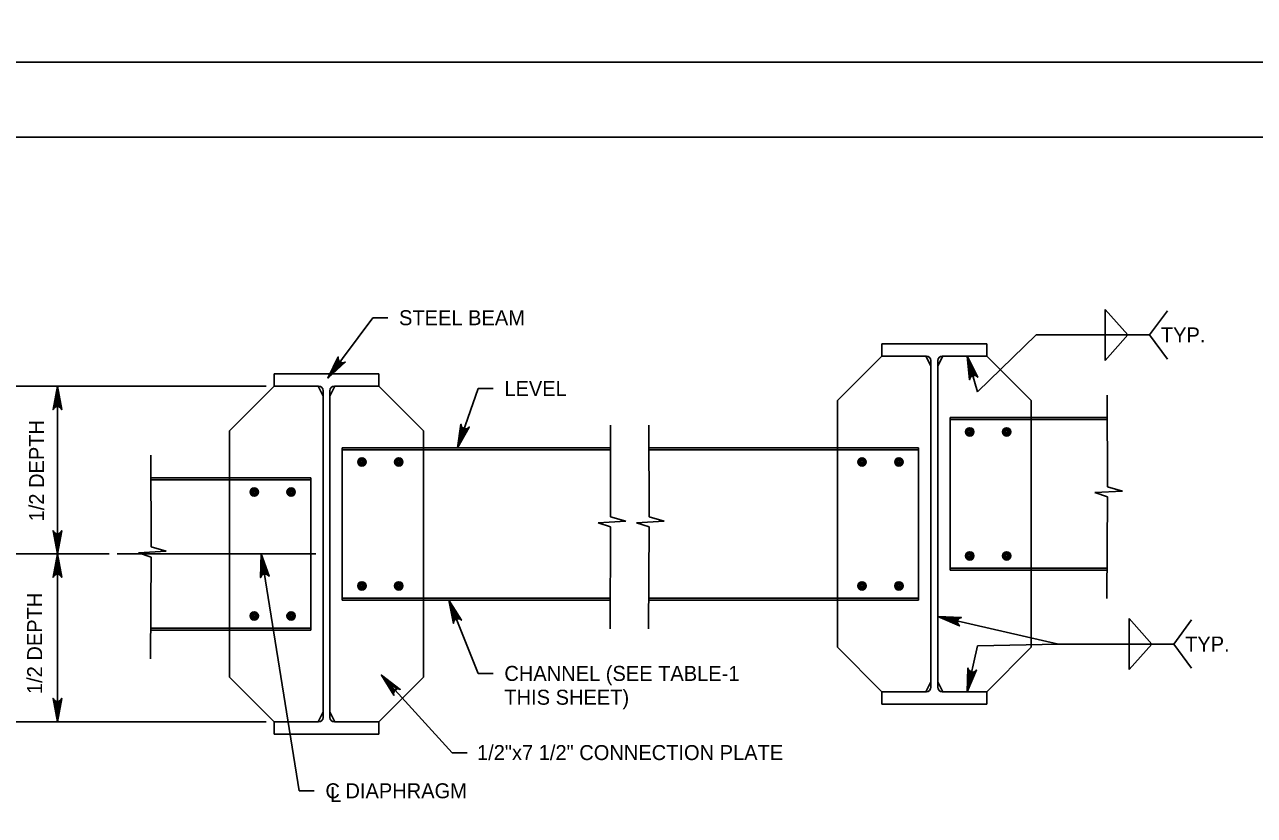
# Model space of a CAD drawing. Extents: x 638175 to 640495, y 294277 to 298435.
# Drawn here: x 639651.7 to 639897.7, y 297690.7 to 297849 of the extents above; entities that cross this region are included whole.
import ezdxf

# ---------------------------------------------------------------- set-up
doc = ezdxf.new("R2010")
doc.units = 0
for name, color, linetype in [('2', 7, 'Continuous'), ('3', 7, 'Continuous'), ('4', 7, 'Continuous'), ('5', 7, 'Continuous'), ('PLT-BNDY', 7, 'Continuous')]:
    doc.layers.add(name, color=color, linetype=linetype)

msp = doc.modelspace()

# ---------------------------------------------------------------- linework, layer by layer
at = {"layer": '2'}
msp.add_line((639316.46, 297826.46), (640102.46, 297826.46), dxfattribs=at)
for points in [[(639658.23, 297776.59), (639659.1, 297771.93), (639658.85, 297772.29), (639658.54, 297772.47), (639658.23, 297772.53), (639657.91, 297772.47), (639657.6, 297772.29), (639657.35, 297771.93), (639658.23, 297776.59), (639657.6, 297772.29), (639657.91, 297772.47), (639658.23, 297776.59), (639658.23, 297772.53), (639658.54, 297772.47), (639658.23, 297776.59), (639658.85, 297772.29)], [(639658.23, 297743.02), (639657.35, 297747.68), (639657.6, 297747.32), (639657.91, 297747.13), (639658.23, 297747.08), (639658.54, 297747.13), (639658.85, 297747.32), (639659.1, 297747.68), (639658.23, 297743.02), (639658.85, 297747.32), (639658.54, 297747.13), (639658.23, 297743.02), (639658.23, 297747.08), (639657.91, 297747.13), (639658.23, 297743.02), (639657.6, 297747.32)], [(639658.23, 297743.02), (639657.35, 297738.36), (639657.6, 297738.71), (639657.91, 297738.9), (639658.23, 297738.95), (639658.54, 297738.9), (639658.85, 297738.71), (639659.1, 297738.36), (639658.23, 297743.02), (639658.85, 297738.71), (639658.54, 297738.9), (639658.23, 297743.02), (639658.23, 297738.95), (639657.91, 297738.9), (639658.23, 297743.02), (639657.6, 297738.71)], [(639658.23, 297709.44), (639657.35, 297714.1), (639657.6, 297713.75), (639657.91, 297713.56), (639658.23, 297713.51), (639658.54, 297713.56), (639658.85, 297713.75), (639659.1, 297714.1), (639658.23, 297709.44), (639658.85, 297713.75), (639658.54, 297713.56), (639658.23, 297709.44), (639658.23, 297713.51), (639657.91, 297713.56), (639658.23, 297709.44), (639657.6, 297713.75)]]:
    msp.add_lwpolyline(points, dxfattribs=at)
at = {"layer": '3'}
for p, q in [((639712.33, 297778.21), (639721.32, 297790.3)), ((639721.32, 297790.3), (639724.32, 297790.3)), ((639867.84, 297791.93), (639872.38, 297786.85)), ((639867.84, 297786.85), (639867.84, 297791.93)), ((639876.75, 297786.85), (639880.32, 297791.69)), ((639842.3, 297775.45), (639854.05, 297786.85)), ((639854.05, 297786.85), (639876.75, 297786.85)), ((639867.84, 297781.76), (639872.38, 297786.85)), ((639867.84, 297786.85), (639867.84, 297781.76)), ((639876.75, 297786.85), (639880.32, 297782.01)), ((639840.22, 297782.6), (639842.3, 297775.45)), ((639700.02, 297776.59), (639634.16, 297776.59)), ((639658.23, 297743.02), (639658.23, 297776.59)), ((639738.25, 297764.29), (639742.4, 297776.14)), ((639742.4, 297776.14), (639745.4, 297776.14)), ((639868.25, 297774.83), (639868.31, 297756.48)), ((639768.85, 297768.82), (639768.91, 297750.46)), ((639776.57, 297768.82), (639776.63, 297750.46)), ((639676.89, 297762.81), (639676.95, 297744.45)), ((639871.31, 297755.6), (639865.79, 297755.29)), ((639865.79, 297755.29), (639868.3, 297754.43)), ((639868.31, 297756.48), (639871.31, 297755.6)), ((639868.3, 297754.43), (639868.18, 297734.08)), ((639768.91, 297750.46), (639771.92, 297749.58)), ((639776.63, 297750.46), (639779.63, 297749.58)), ((639771.92, 297749.58), (639766.4, 297749.28)), ((639766.4, 297749.28), (639768.91, 297748.42)), ((639768.91, 297748.42), (639768.79, 297728.06)), ((639779.63, 297749.58), (639774.11, 297749.28)), ((639774.11, 297749.28), (639776.63, 297748.42)), ((639776.63, 297748.42), (639776.5, 297728.06)), ((639668.59, 297743.02), (639649.76, 297743.02)), ((639658.23, 297709.44), (639658.23, 297743.02)), ((639679.96, 297743.57), (639674.44, 297743.26)), ((639674.44, 297743.26), (639676.95, 297742.41)), ((639676.95, 297744.45), (639679.96, 297743.57)), ((639698.98, 297743.02), (639706.59, 297695.63)), ((639676.95, 297742.41), (639676.83, 297722.05)), ((639736.53, 297733.77), (639742.4, 297719.13)), ((639834.37, 297730.53), (639858.54, 297725)), ((639872.68, 297730.08), (639877.21, 297725)), ((639872.68, 297725), (639872.68, 297730.08)), ((639881.59, 297725), (639885.16, 297729.84)), ((639840.22, 297715.46), (639842.3, 297724.66)), ((639842.3, 297724.66), (639858.54, 297725)), ((639858.54, 297725), (639881.59, 297725)), ((639872.68, 297725), (639872.68, 297719.92)), ((639872.68, 297719.92), (639877.21, 297725)), ((639881.59, 297725), (639885.16, 297720.16)), ((639723.05, 297718.78), (639737.22, 297703.23)), ((639742.4, 297719.13), (639745.4, 297719.13)), ((639700.02, 297709.44), (639634.16, 297709.44)), ((639737.22, 297703.23), (639740.22, 297703.23)), ((639706.59, 297695.63), (639709.59, 297695.63))]:
    msp.add_line(p, q, dxfattribs=at)
for points in [[(639712.33, 297778.21), (639714.41, 297782.47), (639714.39, 297782.04), (639714.53, 297781.7), (639714.75, 297781.47), (639715.03, 297781.33), (639715.4, 297781.29), (639715.81, 297781.43), (639712.33, 297778.21), (639715.4, 297781.29), (639715.03, 297781.33), (639712.33, 297778.21), (639714.75, 297781.47), (639714.53, 297781.7), (639712.33, 297778.21), (639714.39, 297782.04)], [(639840.22, 297782.6), (639842.36, 297778.37), (639842.02, 297778.65), (639841.67, 297778.74), (639841.35, 297778.7), (639841.07, 297778.56), (639840.82, 297778.3), (639840.68, 297777.89), (639840.22, 297782.6), (639840.82, 297778.3), (639841.07, 297778.56), (639840.22, 297782.6), (639841.35, 297778.7), (639841.67, 297778.74), (639840.22, 297782.6), (639842.02, 297778.65)], [(639738.25, 297764.29), (639738.97, 297768.97), (639739.08, 297768.55), (639739.32, 297768.27), (639739.6, 297768.12), (639739.91, 297768.07), (639740.26, 297768.14), (639740.62, 297768.4), (639738.25, 297764.29), (639740.26, 297768.14), (639739.91, 297768.07), (639738.25, 297764.29), (639739.6, 297768.12), (639739.32, 297768.27), (639738.25, 297764.29), (639739.08, 297768.55)], [(639698.98, 297743.02), (639700.58, 297738.55), (639700.28, 297738.87), (639699.94, 297739), (639699.63, 297739.01), (639699.33, 297738.9), (639699.05, 297738.67), (639698.86, 297738.28), (639698.98, 297743.02), (639699.05, 297738.67), (639699.33, 297738.9), (639698.98, 297743.02), (639699.63, 297739.01), (639699.94, 297739), (639698.98, 297743.02), (639700.28, 297738.87)], [(639736.53, 297733.77), (639739.07, 297729.77), (639738.71, 297730.01), (639738.35, 297730.07), (639738.04, 297730), (639737.77, 297729.84), (639737.55, 297729.55), (639737.45, 297729.12), (639736.53, 297733.77), (639737.55, 297729.55), (639737.77, 297729.84), (639736.53, 297733.77), (639738.04, 297730), (639738.35, 297730.07), (639736.53, 297733.77), (639738.71, 297730.01)], [(639834.37, 297730.53), (639839.1, 297730.34), (639838.7, 297730.18), (639838.45, 297729.92), (639838.33, 297729.62), (639838.31, 297729.31), (639838.42, 297728.96), (639838.71, 297728.64), (639834.37, 297730.53), (639838.42, 297728.96), (639838.31, 297729.31), (639834.37, 297730.53), (639838.33, 297729.62), (639838.45, 297729.92), (639834.37, 297730.53), (639838.7, 297730.18)], [(639723.05, 297718.78), (639726.83, 297715.92), (639726.4, 297716.02), (639726.05, 297715.95), (639725.78, 297715.78), (639725.59, 297715.53), (639725.48, 297715.18), (639725.54, 297714.75), (639723.05, 297718.78), (639725.48, 297715.18), (639725.59, 297715.53), (639723.05, 297718.78), (639725.78, 297715.78), (639726.05, 297715.95), (639723.05, 297718.78), (639726.4, 297716.02)], [(639840.22, 297715.46), (639840.4, 297720.2), (639840.56, 297719.79), (639840.82, 297719.54), (639841.12, 297719.42), (639841.43, 297719.4), (639841.78, 297719.52), (639842.1, 297719.81), (639840.22, 297715.46), (639841.78, 297719.52), (639841.43, 297719.4), (639840.22, 297715.46), (639841.12, 297719.42), (639840.82, 297719.54), (639840.22, 297715.46), (639840.56, 297719.79)]]:
    msp.add_lwpolyline(points, dxfattribs=at)
for points in [[(639840.58, 297779.58), (639841.54, 297779.86), (639840.22, 297782.6)], [(639714.52, 297780.32), (639713.72, 297780.92), (639712.33, 297778.21)], [(639657.73, 297773.59), (639658.73, 297773.59), (639658.23, 297776.59)], [(639739.72, 297766.95), (639738.77, 297767.28), (639738.25, 297764.29)], [(639657.73, 297746.02), (639658.73, 297746.02), (639658.23, 297743.02)], [(639657.73, 297740.02), (639658.73, 297740.02), (639658.23, 297743.02)], [(639698.96, 297739.97), (639699.95, 297740.13), (639698.98, 297743.02)], [(639737.18, 297730.8), (639738.11, 297731.18), (639736.52, 297733.77)], [(639837.18, 297729.37), (639837.4, 297730.35), (639834.37, 297730.53)], [(639724.7, 297716.23), (639725.43, 297716.9), (639723.05, 297718.78)], [(639841.37, 297718.27), (639840.4, 297718.5), (639840.22, 297715.46)], [(639657.73, 297712.44), (639658.73, 297712.44), (639658.23, 297709.44)]]:
    msp.add_lwpolyline(points, close=True, dxfattribs=at)
at = {"layer": '4'}
for p, q in [((639844.16, 297785.1), (639823.2, 297785.1)), ((639823.2, 297782.6), (639814.29, 297773.7)), ((639832.1, 297782.6), (639823.2, 297782.6)), ((639832, 297782.6), (639832.99, 297780.64)), ((639835.35, 297782.6), (639834.37, 297780.64)), ((639844.16, 297782.6), (639835.26, 297782.6)), ((639844.16, 297782.6), (639853.07, 297773.7)), ((639832.99, 297781.71), (639832.99, 297716.35)), ((639834.37, 297781.71), (639834.37, 297716.35)), ((639701.58, 297779.09), (639722.55, 297779.09)), ((639701.58, 297776.59), (639692.67, 297767.68)), ((639701.58, 297776.59), (639710.49, 297776.59)), ((639710.39, 297776.59), (639711.38, 297774.62)), ((639711.38, 297775.7), (639711.38, 297710.33)), ((639713.74, 297776.59), (639712.75, 297774.62)), ((639712.75, 297775.7), (639712.75, 297710.33)), ((639713.64, 297776.59), (639722.55, 297776.59)), ((639722.55, 297776.59), (639731.46, 297767.68)), ((639814.29, 297773.7), (639814.29, 297764.29)), ((639853.07, 297773.7), (639853.07, 297770.3)), ((639836.83, 297770.3), (639836.83, 297739.79)), ((639853.07, 297770.3), (639853.07, 297739.79)), ((639692.67, 297767.68), (639692.67, 297758.27)), ((639731.46, 297767.68), (639731.46, 297764.29)), ((639715.21, 297764.29), (639715.21, 297733.77)), ((639731.46, 297764.29), (639731.46, 297733.77)), ((639814.29, 297764.29), (639814.29, 297733.77)), ((639830.53, 297764.29), (639830.53, 297733.77)), ((639692.67, 297758.27), (639692.67, 297727.76)), ((639708.92, 297758.27), (639708.92, 297727.76)), ((639853.07, 297739.79), (639853.07, 297724.37)), ((639731.46, 297733.77), (639731.46, 297718.35)), ((639814.29, 297733.77), (639814.29, 297724.37)), ((639692.67, 297727.76), (639692.67, 297718.35)), ((639814.29, 297724.37), (639823.2, 297715.46)), ((639844.16, 297715.46), (639853.07, 297724.37)), ((639692.67, 297718.35), (639701.58, 297709.44)), ((639722.55, 297709.44), (639731.46, 297718.35)), ((639832, 297715.46), (639832.99, 297717.43)), ((639835.35, 297715.46), (639834.37, 297717.43)), ((639832.1, 297715.46), (639823.2, 297715.46)), ((639844.16, 297715.46), (639835.26, 297715.46)), ((639710.39, 297709.44), (639711.38, 297711.41)), ((639713.74, 297709.44), (639712.75, 297711.41)), ((639844.16, 297712.96), (639823.2, 297712.96)), ((639701.58, 297709.44), (639710.49, 297709.44)), ((639713.64, 297709.44), (639722.55, 297709.44)), ((639701.58, 297706.94), (639722.55, 297706.94))]:
    msp.add_line(p, q, dxfattribs=at)
for centre, radius in [((639840.76, 297767.45), 0.833), ((639840.76, 297767.45), 0.625), ((639840.76, 297767.45), 0.417), ((639840.76, 297767.45), 0.208), ((639848.15, 297767.45), 0.833), ((639848.15, 297767.45), 0.625), ((639848.15, 297767.45), 0.417), ((639848.15, 297767.45), 0.208), ((639719.15, 297761.43), 0.833), ((639719.15, 297761.43), 0.625), ((639719.15, 297761.43), 0.417), ((639719.15, 297761.43), 0.208), ((639726.53, 297761.43), 0.833), ((639726.53, 297761.43), 0.625), ((639726.53, 297761.43), 0.417), ((639726.53, 297761.43), 0.208), ((639819.21, 297761.43), 0.833), ((639819.21, 297761.43), 0.625), ((639819.21, 297761.43), 0.417), ((639819.21, 297761.43), 0.208), ((639826.59, 297761.43), 0.833), ((639826.59, 297761.43), 0.625), ((639826.59, 297761.43), 0.417), ((639826.59, 297761.43), 0.208), ((639697.6, 297755.42), 0.833), ((639697.6, 297755.42), 0.625), ((639697.6, 297755.42), 0.417), ((639697.6, 297755.42), 0.208), ((639704.98, 297755.42), 0.833), ((639704.98, 297755.42), 0.625), ((639704.98, 297755.42), 0.417), ((639704.98, 297755.42), 0.208), ((639840.76, 297742.64), 0.833), ((639840.76, 297742.64), 0.625), ((639840.76, 297742.64), 0.417), ((639848.15, 297742.64), 0.833), ((639848.15, 297742.64), 0.625), ((639848.15, 297742.64), 0.417), ((639840.76, 297742.64), 0.208), ((639848.15, 297742.64), 0.208), ((639719.15, 297736.63), 0.833), ((639719.15, 297736.63), 0.625), ((639719.15, 297736.63), 0.417), ((639719.15, 297736.63), 0.208), ((639726.53, 297736.63), 0.833), ((639726.53, 297736.63), 0.625), ((639726.53, 297736.63), 0.417), ((639726.53, 297736.63), 0.208), ((639819.21, 297736.63), 0.833), ((639819.21, 297736.63), 0.625), ((639819.21, 297736.63), 0.417), ((639819.21, 297736.63), 0.208), ((639826.59, 297736.63), 0.833), ((639826.59, 297736.63), 0.625), ((639826.59, 297736.63), 0.417), ((639826.59, 297736.63), 0.208), ((639697.6, 297730.62), 0.833), ((639697.6, 297730.62), 0.625), ((639697.6, 297730.62), 0.417), ((639697.6, 297730.62), 0.208), ((639704.98, 297730.62), 0.833), ((639704.98, 297730.62), 0.625), ((639704.98, 297730.62), 0.417), ((639704.98, 297730.62), 0.208)]:
    msp.add_circle(centre, radius, dxfattribs=at)
for centre, start, end in [((639832.1, 297781.71), 0, 90), ((639835.25, 297781.71), 90, 180), ((639710.49, 297775.7), 0, 90), ((639713.64, 297775.7), 90, 180), ((639832.1, 297716.35), 270, 0), ((639835.25, 297716.35), 180, 270), ((639710.49, 297710.33), 270, 0), ((639713.64, 297710.33), 180, 270)]:
    msp.add_arc(centre, 0.889, start, end, dxfattribs=at)
at = {"layer": '5'}
for p, q in [((639823.2, 297785.1), (639823.2, 297782.6)), ((639844.16, 297785.1), (639844.16, 297782.6)), ((639701.58, 297779.09), (639701.58, 297776.59)), ((639722.55, 297779.09), (639722.55, 297776.59)), ((639868.26, 297770.3), (639836.83, 297770.3)), ((639868.26, 297769.91), (639836.83, 297769.91)), ((639768.87, 297764.29), (639715.21, 297764.29)), ((639768.87, 297763.89), (639715.21, 297763.89)), ((639830.53, 297764.29), (639776.58, 297764.29)), ((639830.53, 297763.89), (639776.58, 297763.89)), ((639708.92, 297758.27), (639676.9, 297758.27)), ((639708.92, 297757.88), (639676.91, 297757.88)), ((639709.95, 297743.02), (639670.16, 297743.02)), ((639868.22, 297740.18), (639836.83, 297740.18)), ((639868.22, 297739.79), (639836.83, 297739.79)), ((639768.83, 297734.17), (639715.21, 297734.17)), ((639768.82, 297733.77), (639715.21, 297733.77)), ((639830.53, 297734.17), (639776.54, 297734.17)), ((639830.53, 297733.77), (639776.54, 297733.77)), ((639708.92, 297728.15), (639676.86, 297728.15)), ((639708.92, 297727.76), (639676.86, 297727.76)), ((639823.2, 297712.96), (639823.2, 297715.46)), ((639844.16, 297712.96), (639844.16, 297715.46)), ((639701.58, 297706.94), (639701.58, 297709.44)), ((639722.55, 297706.94), (639722.55, 297709.44))]:
    msp.add_line(p, q, dxfattribs=at)
at = {"layer": 'PLT-BNDY'}
for points in [[(639276.46, 298435.46), (640117.46, 298435.46), (640117.46, 297841.46), (639276.46, 297841.46)], [(639276.46, 297841.46), (640117.46, 297841.46), (640117.46, 297247.46), (639276.46, 297247.46)]]:
    msp.add_lwpolyline(points, close=True, dxfattribs=at)

# ---------------------------------------------------------------- texts
at = {"layer": '3'}
for s, p in [('STEEL BEAM', (639726.57, 297788.8)), ('TYP.', (639879, 297785.35)), ('LEVEL', (639747.65, 297774.64)), ('TYP.', (639883.84, 297723.5)), ('CHANNEL (SEE TABLE-1', (639747.65, 297717.62)), ('THIS SHEET)', (639747.65, 297712.85)), ('1/2"x7 1/2" CONNECTION PLATE', (639742.17, 297701.78)), ('C DIAPHRAGM', (639711.84, 297694.13)), ('L', (639712.78, 297693.36))]:
    msp.add_text(s, height=3, dxfattribs=at).set_placement(p)
for p in [(639655.56, 297749.54), (639655.17, 297714.99)]:
    msp.add_text('1/2 DEPTH', height=3, rotation=90, dxfattribs=at).set_placement(p)

doc.saveas('drawing.dxf')
